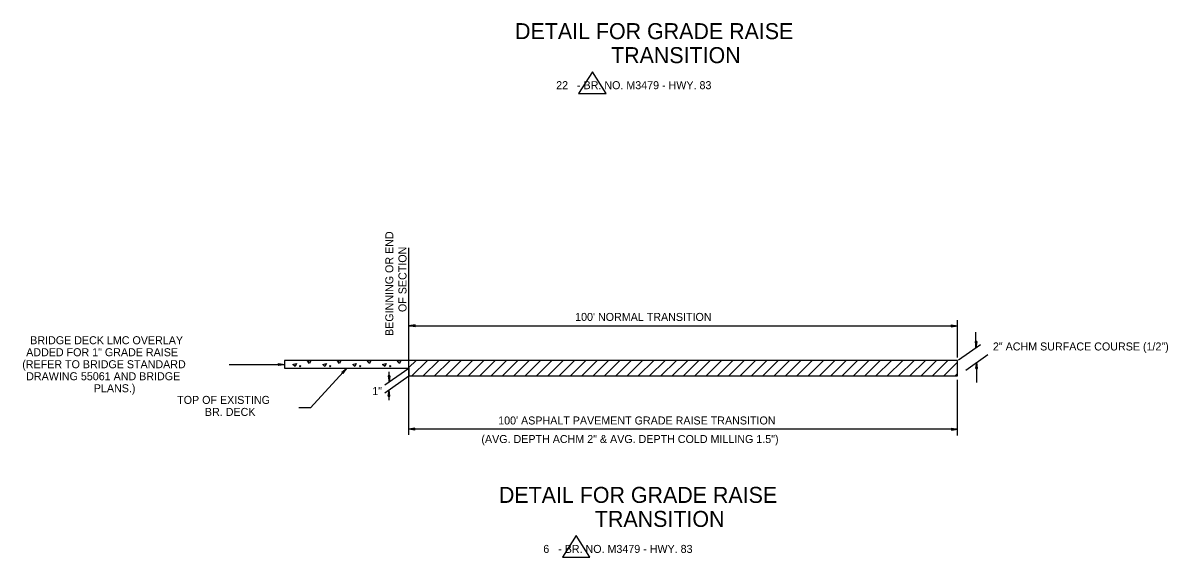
# Model space of a CAD drawing. Extents: x 1931522 to 1935523, y 600380 to 605075.
# Drawn here: x 1931522 to 1932381, y 602335 to 602735 of the extents above; entities that cross this region are included whole.
import ezdxf

# ---------------------------------------------------------------- set-up
doc = ezdxf.new("R2010")
doc.units = 0
for name, color, linetype in [('Default', 7, 'Continuous'), ('R_Border', 7, 'Continuous'), ('R_Draft', 7, 'Continuous')]:
    doc.layers.add(name, color=color, linetype=linetype)

msp = doc.modelspace()

# ---------------------------------------------------------------- linework, layer by layer
at = {"layer": 'Default'}
for p, q in [((1931811.75, 602482.14), (1931811.75, 602566.66)), ((1931816.41, 602508.8), (1931811.75, 602508.13)), ((1931811.75, 602508.13), (1932223.07, 602508.13)), ((1931816.41, 602507.47), (1931811.75, 602508.13)), ((1931816.41, 602508.58), (1931812.42, 602508.13)), ((1931816.41, 602507.47), (1931812.42, 602508.13)), ((1931816.41, 602508.58), (1931813.31, 602508.13)), ((1931816.41, 602507.69), (1931813.31, 602508.13)), ((1931816.41, 602508.35), (1931814.2, 602508.13)), ((1931816.41, 602507.69), (1931814.2, 602508.13)), ((1931816.41, 602508.35), (1931814.87, 602508.13)), ((1931816.41, 602507.92), (1931814.87, 602508.13)), ((1931816.41, 602508.13), (1931815.75, 602508.13)), ((1931816.41, 602507.92), (1931815.75, 602508.13)), ((1931816.41, 602507.47), (1931816.41, 602508.8)), ((1932218.4, 602508.8), (1932223.07, 602508.13)), ((1932218.4, 602508.8), (1932218.4, 602507.47)), ((1932218.4, 602508.58), (1932221.52, 602508.13)), ((1932218.4, 602508.58), (1932222.17, 602508.13)), ((1932218.4, 602508.35), (1932219.95, 602508.13)), ((1932218.4, 602508.35), (1932220.63, 602508.13)), ((1932218.4, 602507.47), (1932223.07, 602508.13)), ((1932218.4, 602507.92), (1932219.95, 602508.13)), ((1932218.4, 602507.69), (1932221.52, 602508.13)), ((1932218.4, 602507.47), (1932222.17, 602508.13)), ((1932218.4, 602507.69), (1932220.63, 602508.13)), ((1932218.4, 602507.92), (1932219.07, 602508.13)), ((1932218.4, 602508.13), (1932219.07, 602508.13)), ((1932223.07, 602484.29), (1932223.07, 602512.28)), ((1932236.18, 602496.38), (1932236.84, 602491.72)), ((1932237.5, 602496.38), (1932236.18, 602496.38)), ((1932236.4, 602496.38), (1932236.84, 602493.28)), ((1932236.4, 602496.38), (1932236.84, 602492.61)), ((1932236.61, 602496.38), (1932236.84, 602494.84)), ((1932236.61, 602496.38), (1932236.84, 602494.17)), ((1932236.84, 602491.72), (1932236.84, 602503.49)), ((1932237.5, 602496.38), (1932236.84, 602491.72)), ((1932237.06, 602496.38), (1932236.84, 602494.84)), ((1932237.29, 602496.38), (1932236.84, 602493.28)), ((1932237.5, 602496.38), (1932236.84, 602492.61)), ((1932237.29, 602496.38), (1932236.84, 602494.17)), ((1932236.84, 602496.38), (1932236.84, 602495.72)), ((1932237.06, 602496.38), (1932236.84, 602495.72)), ((1932223.75, 602482.65), (1932240.39, 602494.17)), ((1931677.04, 602479.1), (1931718.5, 602479.25)), ((1931713.78, 602478.53), (1931713.83, 602479.94)), ((1931713.78, 602478.53), (1931718.5, 602479.25)), ((1931713.79, 602479.64), (1931716.9, 602479.18)), ((1931713.83, 602479.94), (1931718.5, 602479.25)), ((1931713.84, 602478.84), (1931715.48, 602479.22)), ((1931713.84, 602478.84), (1931716.09, 602479.13)), ((1931713.89, 602479.14), (1931714.67, 602479.19)), ((1931713.89, 602479.14), (1931714.67, 602479.19)), ((1931713.93, 602479.45), (1931715.48, 602479.22)), ((1931713.93, 602479.45), (1931716.09, 602479.13)), ((1931713.96, 602479.77), (1931717.7, 602479.22)), ((1931713.97, 602478.67), (1931717.7, 602479.22)), ((1931713.97, 602478.67), (1931716.9, 602479.18)), ((1932229.18, 602474.95), (1932245.72, 602486.61)), ((1932236.79, 602476.11), (1932237.45, 602480.78)), ((1932237.02, 602476.11), (1932237.45, 602480.11)), ((1932237.02, 602476.11), (1932237.45, 602479.22)), ((1932237.45, 602465.68), (1932237.45, 602480.78)), ((1932238.12, 602476.11), (1932237.45, 602480.78)), ((1932238.12, 602476.11), (1932237.45, 602480.11)), ((1932237.9, 602476.11), (1932237.45, 602479.22)), ((1931718.5, 602476.37), (1931811.75, 602476.38)), ((1931737.92, 602446.57), (1931765.12, 602476.37)), ((1931761.46, 602473.4), (1931765.12, 602476.37)), ((1931762.46, 602472.41), (1931761.46, 602473.4)), ((1931761.65, 602473.17), (1931764.09, 602475.15)), ((1931761.67, 602473.38), (1931764.61, 602475.76)), ((1931761.88, 602473.14), (1931763.58, 602474.52)), ((1931761.88, 602473.14), (1931763.1, 602474.13)), ((1931762.08, 602472.9), (1931762.58, 602473.51)), ((1931762.08, 602472.9), (1931762.58, 602473.51)), ((1931762.27, 602472.66), (1931763.58, 602474.52)), ((1931762.27, 602472.66), (1931763.1, 602474.13)), ((1931762.46, 602472.41), (1931765.12, 602476.37)), ((1931762.49, 602472.64), (1931764.61, 602475.76)), ((1931762.49, 602472.64), (1931764.09, 602475.15)), ((1931793.76, 602463.93), (1931811.75, 602476.38)), ((1931793.76, 602457.93), (1931811.75, 602470.6)), ((1931796.14, 602470.66), (1931796.8, 602465.99)), ((1931797.47, 602470.66), (1931796.14, 602470.66)), ((1931796.37, 602470.66), (1931796.8, 602467.55)), ((1931796.37, 602470.66), (1931796.8, 602466.89)), ((1931796.57, 602470.66), (1931796.8, 602469.11)), ((1931796.57, 602470.66), (1931796.8, 602468.44)), ((1931796.8, 602465.99), (1931796.8, 602473.57)), ((1931797.47, 602470.66), (1931796.8, 602465.99)), ((1931797.02, 602470.66), (1931796.8, 602469.11)), ((1931797.25, 602470.66), (1931796.8, 602467.55)), ((1931797.47, 602470.66), (1931796.8, 602466.89)), ((1931797.25, 602470.66), (1931796.8, 602468.44)), ((1931796.8, 602470.66), (1931796.8, 602469.99)), ((1931797.02, 602470.66), (1931796.8, 602469.99)), ((1931811.75, 602426.51), (1931811.75, 602476.38)), ((1932236.79, 602476.11), (1932238.12, 602476.11)), ((1932237.22, 602476.11), (1932237.45, 602478.55)), ((1932237.22, 602476.11), (1932237.45, 602477.66)), ((1932237.9, 602476.11), (1932237.45, 602478.55)), ((1932237.67, 602476.11), (1932237.45, 602477.66)), ((1932237.67, 602476.11), (1932237.45, 602477.01)), ((1932237.45, 602476.11), (1932237.45, 602477.01)), ((1932223.07, 602425.9), (1932223.07, 602467.64)), ((1931796.12, 602455.31), (1931796.78, 602459.98)), ((1931796.12, 602455.31), (1931797.45, 602455.31)), ((1931796.35, 602455.31), (1931796.78, 602459.31)), ((1931796.35, 602455.31), (1931796.78, 602458.41)), ((1931796.55, 602455.31), (1931796.78, 602457.75)), ((1931796.55, 602455.31), (1931796.78, 602456.85)), ((1931797.45, 602455.31), (1931796.78, 602459.98)), ((1931796.78, 602452.42), (1931796.78, 602459.98)), ((1931797.45, 602455.31), (1931796.78, 602459.31)), ((1931797.23, 602455.31), (1931796.78, 602458.41)), ((1931797.23, 602455.31), (1931796.78, 602457.75)), ((1931797, 602455.31), (1931796.78, 602456.85)), ((1931797, 602455.31), (1931796.78, 602456.2)), ((1931796.78, 602455.31), (1931796.78, 602456.2)), ((1931737.92, 602446.57), (1931729.14, 602446.57)), ((1931816.21, 602431.36), (1931811.75, 602430.71)), ((1932223.07, 602430.71), (1931811.75, 602430.71)), ((1931816.21, 602430.04), (1931811.75, 602430.71)), ((1931816.21, 602431.36), (1931812.42, 602430.71)), ((1931816.21, 602430.26), (1931812.42, 602430.71)), ((1931816.21, 602431.16), (1931813.31, 602430.71)), ((1931816.21, 602430.26), (1931813.31, 602430.71)), ((1931816.21, 602431.16), (1931813.97, 602430.71)), ((1931816.21, 602430.48), (1931813.97, 602430.71)), ((1931816.21, 602430.92), (1931814.87, 602430.71)), ((1931816.21, 602430.48), (1931814.87, 602430.71)), ((1931816.21, 602430.92), (1931815.53, 602430.71)), ((1931816.21, 602430.71), (1931815.53, 602430.71)), ((1931816.21, 602430.04), (1931816.21, 602431.36)), ((1932218.63, 602431.36), (1932223.07, 602430.71)), ((1932218.63, 602431.36), (1932222.4, 602430.71)), ((1932218.63, 602431.36), (1932218.63, 602430.04)), ((1932218.63, 602431.16), (1932221.52, 602430.71)), ((1932218.63, 602431.16), (1932220.87, 602430.71)), ((1932218.63, 602430.92), (1932219.97, 602430.71)), ((1932218.63, 602430.92), (1932219.31, 602430.71)), ((1932218.63, 602430.04), (1932223.07, 602430.71)), ((1932218.63, 602430.48), (1932219.97, 602430.71)), ((1932218.63, 602430.26), (1932221.52, 602430.71)), ((1932218.63, 602430.26), (1932222.4, 602430.71)), ((1932218.63, 602430.48), (1932220.87, 602430.71)), ((1932218.63, 602430.71), (1932219.31, 602430.71))]:
    msp.add_line(p, q, dxfattribs=at)
msp.add_lwpolyline([(1931811.75, 602476.38), (1931811.75, 602476.38)], dxfattribs=at)
at = {"layer": 'R_Border'}
for p, q in [((1931949.26, 602698.67), (1931938.91, 602682.45)), ((1931959.61, 602682.45), (1931949.26, 602698.67)), ((1931938.91, 602682.45), (1931959.61, 602682.45)), ((1931797.88, 602482.14), (1931718.5, 602482.14)), ((1931718.5, 602482.14), (1931718.5, 602476.37)), ((1931724.64, 602479.21), (1931727.34, 602479.95)), ((1931726.3, 602477.57), (1931724.64, 602479.21)), ((1931727.34, 602479.95), (1931726.3, 602477.57)), ((1931735.62, 602481.59), (1931737.62, 602482.14)), ((1931737.28, 602479.95), (1931735.62, 602481.59)), ((1931738.25, 602482.14), (1931737.28, 602479.95)), ((1931747.1, 602479.21), (1931749.8, 602479.95)), ((1931748.76, 602477.57), (1931747.1, 602479.21)), ((1931749.8, 602479.95), (1931748.76, 602477.57)), ((1931758.07, 602481.59), (1931760.09, 602482.14)), ((1931759.73, 602479.95), (1931758.07, 602481.59)), ((1931760.7, 602482.14), (1931759.73, 602479.95)), ((1931769.55, 602479.21), (1931772.25, 602479.95)), ((1931771.21, 602477.57), (1931769.55, 602479.21)), ((1931772.25, 602479.95), (1931771.21, 602477.57)), ((1931780.52, 602481.59), (1931782.55, 602482.14)), ((1931782.18, 602479.95), (1931780.52, 602481.59)), ((1931783.16, 602482.14), (1931782.18, 602479.95)), ((1931792, 602479.21), (1931794.7, 602479.95)), ((1931793.66, 602477.57), (1931792, 602479.21)), ((1931794.7, 602479.95), (1931793.66, 602477.57)), ((1931811.75, 602482.14), (1931797.88, 602482.14)), ((1931802.98, 602481.59), (1931805, 602482.14)), ((1931804.64, 602479.95), (1931802.98, 602481.59)), ((1931805.61, 602482.14), (1931804.64, 602479.95)), ((1932223.08, 602482.18), (1931811.75, 602482.14)), ((1932223.08, 602482.18), (1931811.75, 602482.14)), ((1931811.75, 602476.83), (1931817.06, 602482.14)), ((1931811.75, 602476.38), (1931811.75, 602482.14)), ((1931814.01, 602470.6), (1931825.55, 602482.14)), ((1931822.5, 602470.61), (1931834.03, 602482.14)), ((1931830.98, 602470.61), (1931842.52, 602482.14)), ((1931839.47, 602470.61), (1931851.01, 602482.14)), ((1931847.95, 602470.61), (1931859.49, 602482.15)), ((1931856.44, 602470.61), (1931867.98, 602482.15)), ((1931864.93, 602470.61), (1931876.46, 602482.15)), ((1931873.41, 602470.61), (1931884.95, 602482.15)), ((1931881.9, 602470.61), (1931893.44, 602482.15)), ((1931890.39, 602470.61), (1931901.92, 602482.15)), ((1931898.87, 602470.61), (1931910.41, 602482.15)), ((1931907.36, 602470.61), (1931918.9, 602482.15)), ((1931915.84, 602470.61), (1931927.38, 602482.15)), ((1931924.33, 602470.61), (1931935.87, 602482.15)), ((1931932.82, 602470.62), (1931944.35, 602482.15)), ((1931941.3, 602470.62), (1931952.84, 602482.15)), ((1931949.79, 602470.62), (1931961.33, 602482.16)), ((1931958.27, 602470.62), (1931969.81, 602482.16)), ((1931966.76, 602470.62), (1931978.3, 602482.16)), ((1931975.25, 602470.62), (1931986.78, 602482.16)), ((1931983.73, 602470.62), (1931995.27, 602482.16)), ((1931992.22, 602470.62), (1932003.76, 602482.16)), ((1932000.7, 602470.62), (1932012.24, 602482.16)), ((1932009.19, 602470.62), (1932020.73, 602482.16)), ((1932017.68, 602470.62), (1932029.22, 602482.16)), ((1932026.16, 602470.62), (1932037.7, 602482.16)), ((1932034.65, 602470.62), (1932046.19, 602482.16)), ((1932043.13, 602470.63), (1932054.67, 602482.16)), ((1932051.62, 602470.63), (1932063.16, 602482.17)), ((1932060.11, 602470.63), (1932071.65, 602482.17)), ((1932068.59, 602470.63), (1932080.13, 602482.17)), ((1932077.08, 602470.63), (1932088.62, 602482.17)), ((1932085.56, 602470.63), (1932097.1, 602482.17)), ((1932094.05, 602470.63), (1932105.59, 602482.17)), ((1932102.54, 602470.63), (1932114.08, 602482.17)), ((1932111.02, 602470.63), (1932122.56, 602482.17)), ((1932119.51, 602470.63), (1932131.05, 602482.17)), ((1932127.99, 602470.63), (1932139.54, 602482.17)), ((1932136.48, 602470.63), (1932148.02, 602482.17)), ((1932144.97, 602470.63), (1932156.51, 602482.18)), ((1932153.45, 602470.63), (1932164.99, 602482.18)), ((1932161.94, 602470.64), (1932173.48, 602482.18)), ((1932170.42, 602470.64), (1932181.97, 602482.18)), ((1932178.91, 602470.64), (1932190.45, 602482.18)), ((1932187.4, 602470.64), (1932198.94, 602482.18)), ((1932195.88, 602470.64), (1932207.42, 602482.18)), ((1932204.37, 602470.64), (1932215.91, 602482.18)), ((1932212.85, 602470.64), (1932223.08, 602480.86)), ((1932223.09, 602470.64), (1932223.07, 602482.18)), ((1932223.09, 602470.64), (1932223.08, 602482.18)), ((1932223.09, 602470.64), (1932223.08, 602482.18)), ((1931811.75, 602476.38), (1931811.75, 602470.6)), ((1931811.75, 602476.38), (1931811.75, 602470.61)), ((1931811.75, 602470.6), (1932223.09, 602470.64)), ((1932221.32, 602470.62), (1932223.09, 602472.39)), ((1932223.09, 602470.64), (1932223.09, 602470.64)), ((1931937.13, 602350.97), (1931926.78, 602334.75)), ((1931947.48, 602334.75), (1931937.13, 602350.97)), ((1931926.78, 602334.75), (1931947.48, 602334.75))]:
    msp.add_line(p, q, dxfattribs=at)
msp.add_lwpolyline([(1931718.5, 602476.37), (1931811.75, 602476.38)], dxfattribs=at)
for centre in [(1931730.23, 602477.9), (1931730.23, 602477.9), (1931752.69, 602477.9), (1931752.69, 602477.9), (1931775.14, 602477.9), (1931775.14, 602477.9), (1931797.59, 602477.9), (1931797.59, 602477.9)]:
    msp.add_ellipse(centre, major_axis=(0, 0.411), ratio=0.9997, dxfattribs=at)

# ---------------------------------------------------------------- texts
at = {"layer": 'Default'}
for s, height, rotation, p in [('DETAIL FOR GRADE RAISE', 12, 360, (1931891.31, 602723.09)), ('TRANSITION', 12, 360, (1931963.29, 602705.09)), ('BEGINNING OR END', 6, 90, (1931800.01, 602500.53)), ('OF SECTION', 6, 90, (1931809.88, 602518.47)), ("100' NORMAL TRANSITION ", 6, 360, (1931936.35, 602511.82)), ('BRIDGE DECK LMC OVERLAY ', 6, 360, (1931527.76, 602494.34)), ('ADDED FOR 1" GRADE RAISE', 6, 360, (1931524.73, 602485.34)), ('(REFER TO BRIDGE STANDARD', 6, 360, (1931521.77, 602476.34)), ('DRAWING 55061 AND BRIDGE', 6, 360, (1931524.73, 602467.34)), (' PLANS.)', 6, 360, (1931573.21, 602458.34)), ('1"', 6, 360, (1931784.2, 602456.2)), ('TOP OF EXISTING ', 6, 360, (1931637.96, 602449.6)), ('BR. DECK', 6, 360, (1931658.75, 602440.6)), ("100' ASPHALT PAVEMENT GRADE RAISE TRANSITION", 6, 360, (1931878.65, 602434.18)), ('(AVG. DEPTH ACHM 2" & AVG. DEPTH COLD MILLING 1.5")', 6, 360, (1931866.06, 602420.27)), ('DETAIL FOR GRADE RAISE', 12, 360, (1931879.19, 602375.39)), ('TRANSITION', 12, 360, (1931951.16, 602357.39))]:
    msp.add_text(s, height=height, rotation=rotation, dxfattribs=at).set_placement(p)
msp.add_text('2" ACHM SURFACE COURSE (1/2")', height=6, dxfattribs=at).set_placement((1932249.6, 602489.68))
at = {"layer": 'R_Draft'}
for s, p in [('      22   - BR. NO. M3479 - HWY. 83', (1931908.77, 602685.57)), ('      6   - BR. NO. M3479 - HWY. 83', (1931899.1, 602337.88))]:
    msp.add_text(s, height=6, dxfattribs=at).set_placement(p)

doc.saveas('drawing.dxf')
